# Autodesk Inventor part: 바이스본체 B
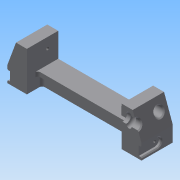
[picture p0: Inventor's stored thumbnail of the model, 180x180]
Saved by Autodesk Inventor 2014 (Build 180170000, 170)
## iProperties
Created: 2017-04
Part Number: 바이스본체 B
Material: 알루미늄 6061
Document SubType Name: Modeling
Designer: mduedu
Density: 2.71 g/cm^3
Appearance: 기본값
Mass: 246.705 g
Surface Area: 210.66 cm^2
Volume: 91.0351 cm^3
Author: mduedu
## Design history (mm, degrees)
sketch "스케치1"
  geometry: L1 (-75, 0)-(75, 0); L2 (-75, 0)-(-75, 17); L3 (-53, 17)-(53, 17); L4 (75, 17)-(75, 0); L5 (-75, 17)-(-65.173, 44); L6 (-65.173, 44)-(-53, 44); L7 (-53, 44)-(-53, 17); L8 (0, 0)-(0, 17); L9 (75, 17)-(65.173, 44); L10 (65.173, 44)-(53, 44); L11 (53, 44)-(53, 17); 1 further point
  constraints: 22 end point, 4 perpendicular, 2 horizontal alignment, 2 midpoint, 2 symmetric about line, 1 coincident, 1 collinear, 1 horizontal, 1 vertical
  dimensions: "d0" = 150 distance of L1.start L1.end; "d1" = 17 distance of L1.start L2.end; "d2" = 27 distance of L3.start L6.end; "d3" = 22 distance of L3.start L2.end; "d4" = 70 deg angle of L3 L5; "d54" = 20 deg angle of L9 L4
extrude "돌출1" new body sketch "스케치1" stored distance "d5" = 70; taper "d6" = 0 deg
sketch "스케치2"
  geometry: L1 (0, 70)-(106, 70) reference; L2 (106, 70)-(106, 0) reference; L3 (106, 0)-(0, 0) reference; L4 (0, 47)-(106, 47); L5 (106, 47)-(106, 23); L6 (106, 23)-(0, 23); L7 (0, 23)-(0, 47); L8 (0, 70)-(0, 0) reference; 2 further points
  constraints: 8 end point, 2 parallel, 2 point on line, 1 horizontal, 1 horizontal alignment, 1 midpoint, 1 perpendicular
  dimensions: "d7" = 24 distance between parallel lines of L6 L4
extrude "돌출2" cut sketch "스케치2" stored distance "d9" = 70; taper "d10" = 0 deg
sketch "스케치3"
  geometry: L1 (22, -23)-(128, -23) reference; L2 (128, -47)-(22, -47) reference; L3 (22, -18)-(128, -18); L4 (128, -52)-(22, -52); L5 (22, -18)-(22, -52); L6 (128, -18)-(128, -52); 1 further point
  constraints: 8 end point, 3 parallel, 2 point on line, 1 perpendicular
  dimensions: "d11" = 5 distance between parallel lines of L3 L1; "d12" = 5 distance between parallel lines of L4 L2
extrude "돌출3" cut sketch "스케치3" distance "d13" = 12; taper "d14" = 0 deg
fillet "모깎기1" dims "d15" = 3, "d16" = 3
sketch "스케치4"
  geometry: L1 (103, 23)-(3, 23) reference; L2 (0, 26)-(0, 0) reference; L3 (106, 0)-(0, 0) reference; L4 (106, 26)-(106, 0) reference; L5 (96, 0)-(90, 0); L6 (90, 0)-(90, 19.5); L7 (96, 19.5)-(96, 0); L8 (90, 19.5)-(96, 19.5); A1 r 3 centre (3, 26) between (0, 26) and (3, 23) reference; A2 r 3 centre (103, 26) between (103, 23) and (106, 26) reference; 1 further point
  constraints: 8 end point, 2 perpendicular, 1 horizontal, 1 parallel, 1 point on line
  dimensions: "d17" = 10 distance between parallel lines of L7 L4; "d18" = 6 distance between parallel lines of L7 L6; "d27" = 3.5 distance between parallel lines of L8 L1
extrude "돌출4" join sketch "스케치4" distance "d19" = 12; taper "d20" = 0 deg
chamfer "모따기1" distance "d21" = 3; stored, may be unused: second distance "d22" = 2, angle "d23" = 45 deg
chamfer "모따기2" distance "d24" = 3; stored, may be unused: second distance "d25" = 2, angle "d26" = 45 deg
sketch "스케치5"
  geometry: L1 (-15.5, 35.8)-(-15.5, -25.8) reference; L2 (19.5, 0)-(0, 0) reference; C1 r 6.5 at (9.5, 15); 1 further point
  constraints: 1 centre point
  dimensions: "d28" = 13 diameter of C1; "d30" = 15 distance from line of C1.centre L2; "d31" = 25 distance from line of C1.centre L1
extrude "돌출5" cut sketch "스케치5" stored distance "d32" = 12; taper "d33" = 0 deg
sketch "스케치6"
  geometry: C1 r 5 at (-10, 15); C2 r 5 at (-60, 15); A1 r 6.5 centre (-10, 15) between (-15.766, 12) and (-4.234, 12) reference; A2 r 6.5 centre (-60, 15) between (-65.766, 12) and (-54.234, 12) reference; 1 further point
  constraints: 2 centre point, 2 coincident
  dimensions: "d34" = 10 diameter of C1; "d35" = 10 diameter of C2 (= d34)
extrude "돌출6" cut sketch "스케치6" stored distance "d36" = 12; taper "d37" = 0 deg
chamfer "모따기3" distance "d38" = 1; stored, may be unused: second distance "d39" = 2, angle "d40" = 45 deg
chamfer "모따기4" distance "d41" = 1; stored, may be unused: second distance "d42" = 2, angle "d43" = 45 deg
sketch "스케치7"
  geometry: L1 (-35, 35.8)-(-35, -25.8) reference; L2 (-70, 0)-(0, 0) reference; C1 r 5 at (-35, 15); 1 further point
  constraints: 1 centre point, 1 point on line
  dimensions: "d44" = 10 diameter of C1; "d45" = 15 distance from line of C1.centre L2
extrude "돌출7" cut sketch "스케치7" stored distance "d46" = 12; taper "d47" = 0 deg
chamfer "모따기5" distance "d48" = 1; stored, may be unused: second distance "d49" = 2, angle "d50" = 45 deg
node "작업축1"
sketch "스케치8"
  geometry: L1 (-105, 32)-(105, 32) reference; L2 (58, 32)-(64, 32); L3 (64, 32)-(64, 40); L4 (64, 40)-(58, 40); L5 (58, 40)-(58, 32); L6 (53, 38)-(53, 26) reference; 1 further point
  constraints: 8 end point, 2 parallel, 1 horizontal, 1 perpendicular, 1 point on line
  dimensions: "d51" = 5 distance from line of L6 L2.start; "d52" = 6 distance of L3.end L4.end; "d53" = 16 diameter of L4 L1
revolve "회전1" sketch "스케치8" stored, may be unused: angle "d55" = 90 deg
fillet "모깎기2"
chamfer "모따기6" distance "d56" = 1; stored, may be unused: second distance "d57" = 2, angle "d58" = 45 deg
sketch "스케치9"
  geometry: L1 (17.5, 3)-(52.5, 3); L2 (52.5, 13)-(17.5, 13); L3 (70, 0)-(0, 0) reference; L4 (17.5, 8)-(52.5, 8); A1 r 5 centre (17.5, 8) between (17.5, 13) and (17.5, 3); A2 r 5 centre (52.5, 8) between (52.5, 3) and (52.5, 13); 3 further points
  constraints: 6 end point, 4 point on circle, 3 tangent, 2 centre point, 2 midpoint, 2 parallel, 1 horizontal, 1 vertical alignment
  dimensions: "d59" = 35 distance of L4.start L4.end; "d61" = 5 radius of A2; "d62" = 8 distance between parallel lines of L3 L4
extrude "돌출8" cut sketch "스케치9" distance "d63" = 3; taper "d64" = 0 deg
chamfer "모따기7" distance "d65" = 1; stored, may be unused: second distance "d66" = 2, angle "d67" = 45 deg
chamfer "모따기8" distance "d68" = 1; stored, may be unused: second distance "d69" = 2, angle "d70" = 45 deg
feature "분할1"
sketch "스케치10"
  geometry: A1 r 5 centre (0, 0) between (0, 5) and (0, -5) reference; 1 further point
  constraints: 1 coincident
hole "구멍1" sketch "스케치10" at (0, 0) diameter "d71" = 2.459; stored, may be unused: countersink angle "d75" = 90 deg, drill point angle "d77" = 120 deg; dims "d72" = 4.5, "d73" = 4, "d74" = 2, "d76" = 6
sketch "스케치11"
  geometry: L1 (0, 0)-(0, 27) reference; L2 (0, 27)-(-35, 27) reference; 2 further points
  dimensions: "d78" = 12 distance from line of point (-12, 15.5) L1; "d79" = 11.5 distance from line of point (-12, 15.5) L2
hole "구멍2" sketch "스케치11" at (-12, 15.5) diameter "d80" = 3.242; stored, may be unused: countersink angle "d84" = 90 deg, drill point angle "d86" = 120 deg; dims "d81" = 6, "d82" = 4, "d83" = 2, "d85" = 8
node "솔리드1"
mirror "대칭1"
mirror "대칭2"
mirror "대칭3"
mirror "대칭4"
node "투영된 루프1"
